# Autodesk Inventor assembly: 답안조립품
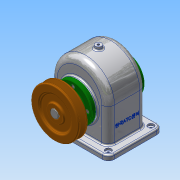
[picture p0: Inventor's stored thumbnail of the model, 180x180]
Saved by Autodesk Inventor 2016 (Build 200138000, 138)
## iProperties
Created: 2018-08
Part Number: 답안조립품
Material: 일반
Document SubType Name: Assembly
Designer: Administrator
Author: Administrator
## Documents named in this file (14)
- C:\Users\Administrator\Desktop\480811V1015\답안조립품.iam
- C:\Users\Administrator\Desktop\480811V1015\본체.ipt
- C:\Users\Administrator\Desktop\480811V1015\뒤커버.ipt
- C:\Users\Administrator\Desktop\480811V1015\베어링 6203.ipt
- C:\Users\Administrator\Desktop\480811V1015\스퍼기어.ipt
- C:\Users\Administrator\Desktop\480811V1015\축.ipt
- C:\Users\Administrator\Desktop\480811V1015\키 6x6x22.ipt
- C:\Users\Administrator\Desktop\480811V1015\앞커버.ipt
- C:\Users\Administrator\Desktop\480811V1015\부시.ipt
- C:\Users\Administrator\Desktop\480811V1015\오일 실 28 40 8.ipt
- C:\Users\Administrator\Desktop\480811V1015\키 5x5x18.ipt
- C:\Users\Administrator\Desktop\480811V1015\V-벨트풀리.ipt
- C:\Users\Administrator\Desktop\480811V1015\멈춤나사 M4.ipt
- C:\Users\Administrator\Desktop\480811V1015\볼트 M4.ipt
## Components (1 placed, 1 different names)
1. V-벨트풀리:1
